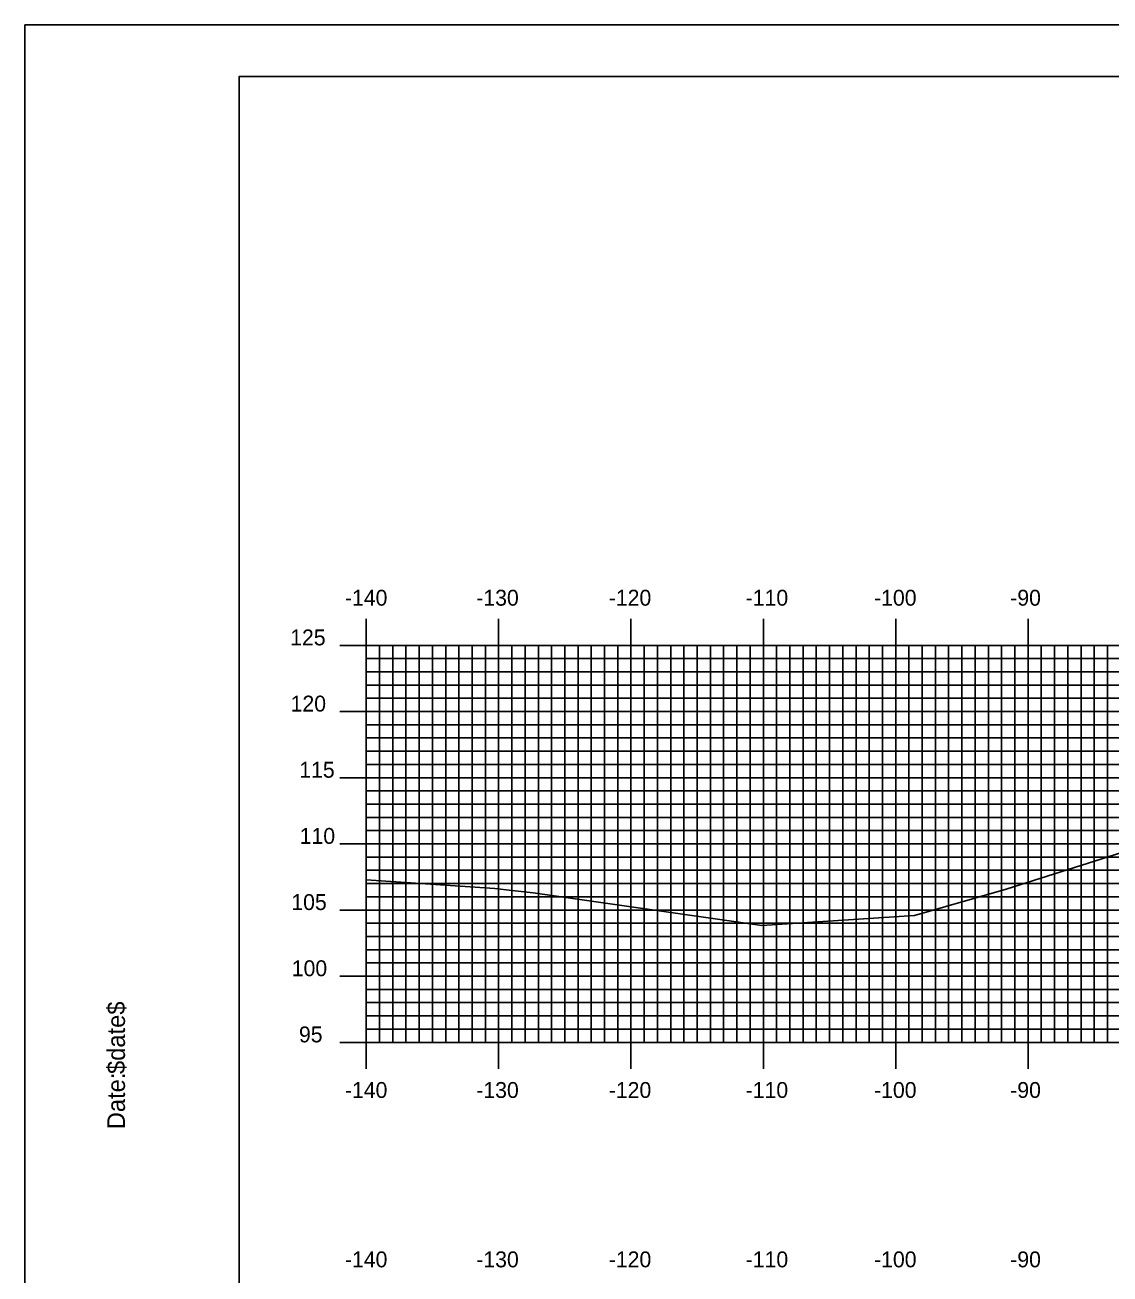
# Model space of a CAD drawing. Extents: x 1684405 to 1684749, y 461260 to 461480.
# Drawn here: x 1684405.4 to 1684487.4, y 461385.6 to 461480 of the extents above; entities that cross this region are included whole.
import ezdxf

# ---------------------------------------------------------------- set-up
doc = ezdxf.new("R2010")
doc.units = 0
for name, color, linetype in [('BORDER', 7, 'Continuous'), ('H_V ANNOTATION', 7, 'Continuous'), ('MAJOR', 7, 'Continuous'), ('MINOR', 7, 'Continuous'), ('PLOT BOUNDARY', 7, 'Continuous'), ('S_Roadway_Centerline', 7, 'Continuous')]:
    doc.layers.add(name, color=color, linetype=linetype)

msp = doc.modelspace()

# ---------------------------------------------------------------- linework, layer by layer
at = {"layer": 'BORDER'}
msp.add_lwpolyline([(1684421.603, 461266.072), (1684741.603, 461266.072), (1684741.603, 461476.072), (1684421.603, 461476.072)], close=True, dxfattribs=at)
at = {"layer": 'MAJOR'}
for p, q in [((1684431.203, 461435.076), (1684431.203, 461433.072)), ((1684441.203, 461435.076), (1684441.203, 461433.072)), ((1684451.203, 461435.076), (1684451.203, 461433.072)), ((1684461.203, 461435.076), (1684461.203, 461433.072)), ((1684471.203, 461435.076), (1684471.203, 461433.072)), ((1684481.203, 461435.076), (1684481.203, 461433.072)), ((1684429.199, 461433.072), (1684431.203, 461433.072)), ((1684431.203, 461433.072), (1684711.203, 461433.072)), ((1684431.203, 461403.072), (1684431.203, 461433.072)), ((1684431.203, 461403.072), (1684431.203, 461433.072)), ((1684431.203, 461433.072), (1684711.203, 461433.072)), ((1684441.203, 461403.072), (1684441.203, 461433.072)), ((1684451.203, 461403.072), (1684451.203, 461433.072)), ((1684461.203, 461403.072), (1684461.203, 461433.072)), ((1684471.203, 461403.072), (1684471.203, 461433.072)), ((1684481.203, 461403.072), (1684481.203, 461433.072)), ((1684429.199, 461428.072), (1684431.203, 461428.072)), ((1684431.203, 461428.072), (1684711.203, 461428.072)), ((1684429.199, 461423.072), (1684431.203, 461423.072)), ((1684431.203, 461423.072), (1684711.203, 461423.072)), ((1684429.199, 461418.072), (1684431.203, 461418.072)), ((1684431.203, 461418.072), (1684711.203, 461418.072)), ((1684429.199, 461413.072), (1684431.203, 461413.072)), ((1684431.203, 461413.072), (1684711.203, 461413.072)), ((1684429.199, 461408.072), (1684431.203, 461408.072)), ((1684431.203, 461408.072), (1684711.203, 461408.072)), ((1684429.199, 461403.072), (1684431.203, 461403.072)), ((1684431.203, 461403.072), (1684711.203, 461403.072)), ((1684431.203, 461403.072), (1684711.203, 461403.072)), ((1684431.203, 461401.068), (1684431.203, 461403.072)), ((1684441.203, 461401.068), (1684441.203, 461403.072)), ((1684451.203, 461401.068), (1684451.203, 461403.072)), ((1684461.203, 461401.068), (1684461.203, 461403.072)), ((1684471.203, 461401.068), (1684471.203, 461403.072)), ((1684481.203, 461401.068), (1684481.203, 461403.072))]:
    msp.add_line(p, q, dxfattribs=at)
at = {"layer": 'MINOR'}
for p, q in [((1684432.203, 461403.072), (1684432.203, 461433.072)), ((1684433.203, 461403.072), (1684433.203, 461433.072)), ((1684434.203, 461403.072), (1684434.203, 461433.072)), ((1684435.203, 461403.072), (1684435.203, 461433.072)), ((1684436.203, 461403.072), (1684436.203, 461433.072)), ((1684437.203, 461403.072), (1684437.203, 461433.072)), ((1684438.203, 461403.072), (1684438.203, 461433.072)), ((1684439.203, 461403.072), (1684439.203, 461433.072)), ((1684440.203, 461403.072), (1684440.203, 461433.072)), ((1684442.203, 461403.072), (1684442.203, 461433.072)), ((1684443.203, 461403.072), (1684443.203, 461433.072)), ((1684444.203, 461403.072), (1684444.203, 461433.072)), ((1684445.203, 461403.072), (1684445.203, 461433.072)), ((1684446.203, 461403.072), (1684446.203, 461433.072)), ((1684447.203, 461403.072), (1684447.203, 461433.072)), ((1684448.203, 461403.072), (1684448.203, 461433.072)), ((1684449.203, 461403.072), (1684449.203, 461433.072)), ((1684450.203, 461403.072), (1684450.203, 461433.072)), ((1684452.203, 461403.072), (1684452.203, 461433.072)), ((1684453.203, 461403.072), (1684453.203, 461433.072)), ((1684454.203, 461403.072), (1684454.203, 461433.072)), ((1684455.203, 461403.072), (1684455.203, 461433.072)), ((1684456.203, 461403.072), (1684456.203, 461433.072)), ((1684457.203, 461403.072), (1684457.203, 461433.072)), ((1684458.203, 461403.072), (1684458.203, 461433.072)), ((1684459.203, 461403.072), (1684459.203, 461433.072)), ((1684460.203, 461403.072), (1684460.203, 461433.072)), ((1684462.203, 461403.072), (1684462.203, 461433.072)), ((1684463.203, 461403.072), (1684463.203, 461433.072)), ((1684464.203, 461403.072), (1684464.203, 461433.072)), ((1684465.203, 461403.072), (1684465.203, 461433.072)), ((1684466.203, 461403.072), (1684466.203, 461433.072)), ((1684467.203, 461403.072), (1684467.203, 461433.072)), ((1684468.203, 461403.072), (1684468.203, 461433.072)), ((1684469.203, 461403.072), (1684469.203, 461433.072)), ((1684470.203, 461403.072), (1684470.203, 461433.072)), ((1684472.203, 461403.072), (1684472.203, 461433.072)), ((1684473.203, 461403.072), (1684473.203, 461433.072)), ((1684474.203, 461403.072), (1684474.203, 461433.072)), ((1684475.203, 461403.072), (1684475.203, 461433.072)), ((1684476.203, 461403.072), (1684476.203, 461433.072)), ((1684477.203, 461403.072), (1684477.203, 461433.072)), ((1684478.203, 461403.072), (1684478.203, 461433.072)), ((1684479.203, 461403.072), (1684479.203, 461433.072)), ((1684480.203, 461403.072), (1684480.203, 461433.072)), ((1684482.203, 461403.072), (1684482.203, 461433.072)), ((1684483.203, 461403.072), (1684483.203, 461433.072)), ((1684484.203, 461403.072), (1684484.203, 461433.072)), ((1684485.203, 461403.072), (1684485.203, 461433.072)), ((1684486.203, 461403.072), (1684486.203, 461433.072)), ((1684487.203, 461403.072), (1684487.203, 461433.072)), ((1684431.203, 461432.072), (1684711.203, 461432.072)), ((1684431.203, 461432.072), (1684433.207, 461432.072)), ((1684431.203, 461431.072), (1684711.203, 461431.072)), ((1684431.203, 461431.072), (1684433.207, 461431.072)), ((1684431.203, 461430.072), (1684711.203, 461430.072)), ((1684431.203, 461430.072), (1684433.207, 461430.072)), ((1684431.203, 461429.072), (1684711.203, 461429.072)), ((1684431.203, 461429.072), (1684433.207, 461429.072)), ((1684431.203, 461427.072), (1684711.203, 461427.072)), ((1684431.203, 461427.072), (1684433.207, 461427.072)), ((1684431.203, 461426.072), (1684711.203, 461426.072)), ((1684431.203, 461426.072), (1684433.207, 461426.072)), ((1684431.203, 461425.072), (1684711.203, 461425.072)), ((1684431.203, 461425.072), (1684433.207, 461425.072)), ((1684431.203, 461424.072), (1684711.203, 461424.072)), ((1684431.203, 461424.072), (1684433.207, 461424.072)), ((1684431.203, 461422.072), (1684711.203, 461422.072)), ((1684431.203, 461422.072), (1684433.207, 461422.072)), ((1684431.203, 461421.072), (1684711.203, 461421.072)), ((1684431.203, 461421.072), (1684433.207, 461421.072)), ((1684431.203, 461420.072), (1684711.203, 461420.072)), ((1684431.203, 461420.072), (1684433.207, 461420.072)), ((1684431.203, 461419.072), (1684711.203, 461419.072)), ((1684431.203, 461419.072), (1684433.207, 461419.072)), ((1684431.203, 461417.072), (1684711.203, 461417.072)), ((1684431.203, 461417.072), (1684433.207, 461417.072)), ((1684431.203, 461416.072), (1684711.203, 461416.072)), ((1684431.203, 461416.072), (1684433.207, 461416.072)), ((1684431.203, 461415.072), (1684711.203, 461415.072)), ((1684431.203, 461415.072), (1684433.207, 461415.072)), ((1684431.203, 461414.072), (1684711.203, 461414.072)), ((1684431.203, 461414.072), (1684433.207, 461414.072)), ((1684431.203, 461412.072), (1684711.203, 461412.072)), ((1684431.203, 461412.072), (1684433.207, 461412.072)), ((1684431.203, 461411.072), (1684711.203, 461411.072)), ((1684431.203, 461411.072), (1684433.207, 461411.072)), ((1684431.203, 461410.072), (1684711.203, 461410.072)), ((1684431.203, 461410.072), (1684433.207, 461410.072)), ((1684431.203, 461409.072), (1684711.203, 461409.072)), ((1684431.203, 461409.072), (1684433.207, 461409.072)), ((1684431.203, 461407.072), (1684711.203, 461407.072)), ((1684431.203, 461407.072), (1684433.207, 461407.072)), ((1684431.203, 461406.072), (1684711.203, 461406.072)), ((1684431.203, 461406.072), (1684433.207, 461406.072)), ((1684431.203, 461405.072), (1684711.203, 461405.072)), ((1684431.203, 461405.072), (1684433.207, 461405.072)), ((1684431.203, 461404.072), (1684711.203, 461404.072)), ((1684431.203, 461404.072), (1684433.207, 461404.072))]:
    msp.add_line(p, q, dxfattribs=at)
at = {"layer": 'PLOT BOUNDARY'}
msp.add_lwpolyline([(1684405.417, 461259.954), (1684745.417, 461259.954), (1684745.417, 461479.954), (1684405.417, 461479.954)], close=True, dxfattribs=at)
at = {"layer": 'S_Roadway_Centerline'}
msp.add_lwpolyline([(1684431.203, 461415.365), (1684440.904, 461414.709), (1684441.773, 461414.6), (1684443.817, 461414.367), (1684461.088, 461411.901), (1684472.612, 461412.669), (1684479.557, 461414.654), (1684489.875, 461417.926)], dxfattribs=at)

# ---------------------------------------------------------------- texts
at = {"layer": 'BORDER'}
for s, p in [('$date$', (1684412.973, 461400.682)), ('Date:', (1684412.973, 461396.506))]:
    msp.add_text(s, height=1.3392, rotation=90, dxfattribs=at).set_placement(p)
at = {"layer": 'H_V ANNOTATION'}
for s, p in [('-140', (1684429.587, 461436.072)), ('-130', (1684439.512, 461436.072)), ('-120', (1684449.523, 461436.072)), ('-110', (1684459.866, 461436.072)), ('-100', (1684469.566, 461436.072)), ('-90', (1684479.855, 461436.072)), ('125', (1684425.452, 461433.072)), ('120', (1684425.484, 461428.072)), ('115', (1684426.138, 461423.072)), ('110', (1684426.17, 461418.072)), ('105', (1684425.538, 461413.072)), ('100', (1684425.57, 461408.072)), ('95', (1684426.116, 461403.072)), ('-140', (1684429.587, 461398.872)), ('-130', (1684439.512, 461398.872)), ('-120', (1684449.523, 461398.872)), ('-110', (1684459.866, 461398.872)), ('-100', (1684469.566, 461398.872)), ('-90', (1684479.855, 461398.872)), ('-140', (1684429.587, 461386.072)), ('-130', (1684439.512, 461386.072)), ('-120', (1684449.523, 461386.072)), ('-110', (1684459.866, 461386.072)), ('-100', (1684469.566, 461386.072)), ('-90', (1684479.855, 461386.072))]:
    msp.add_text(s, height=1.2, dxfattribs=at).set_placement(p)
at = {"layer": 'MAJOR'}
msp.add_text('-', height=0.012, dxfattribs=at).set_placement((1684431.194, 461403.072))

doc.saveas('drawing.dxf')
